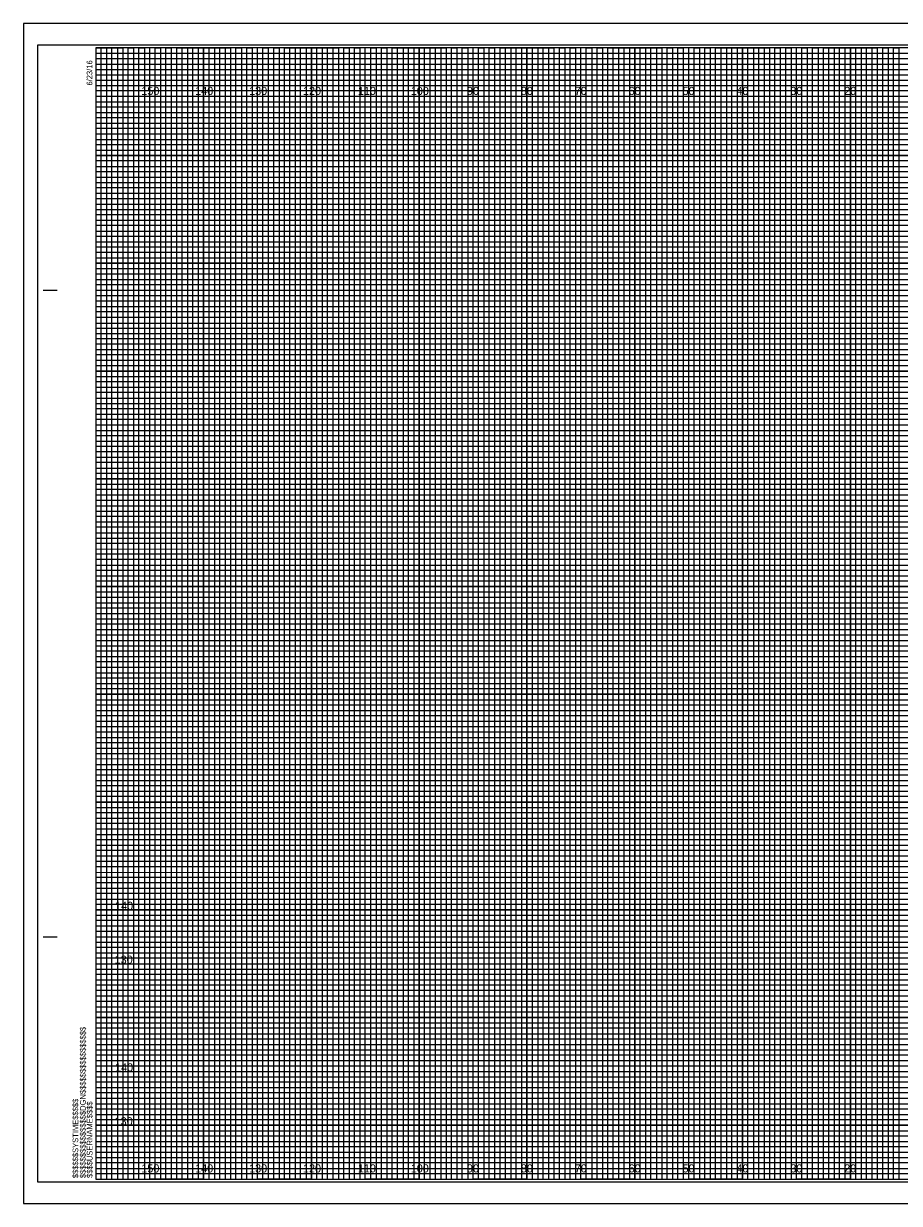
# Model space of a CAD drawing. Extents: x -13 to 323, y -5 to 2634.
# Drawn here: x -13.4 to 149.1, y 2415.5 to 2634.5 of the extents above; entities that cross this region are included whole.
import ezdxf

# ---------------------------------------------------------------- set-up
doc = ezdxf.new("R2010")
doc.units = 0
for name, color, linetype in [('Exist Cross Section Cell', 7, 'Continuous'), ('Exist XS Center Line Elevation Label', 7, 'Continuous'), ('Exist XS Ground Line', 7, 'Continuous'), ('Prop CMT Pvmt Surface Shoulder', 7, 'Continuous'), ('Prop CMT Pvmt Wedge Surface 3', 7, 'Continuous'), ('Prop CMT Shld Paved Course 1', 7, 'Continuous'), ('Prop CMT Shld Paved Course 2', 7, 'Continuous'), ('Prop CMT Shld Paved Course 3', 7, 'Continuous'), ('Prop CMT Slope Grass', 7, 'Continuous'), ('Prop CMT Subgrade Earthwork', 7, 'Continuous'), ('Scratch_Level_0', 7, 'Continuous')]:
    doc.layers.add(name, color=color, linetype=linetype)

msp = doc.modelspace()

# ---------------------------------------------------------------- linework, layer by layer
at = {"layer": 'Exist XS Center Line Elevation Label'}
for points in [[(0, 2630), (5, 2630), (5, 2420), (15, 2420), (15, 2630), (25, 2630), (25, 2420), (35, 2420), (35, 2630), (45, 2630), (45, 2420), (55, 2420), (55, 2630), (65, 2630), (65, 2420), (75, 2420), (75, 2630), (85, 2630), (85, 2420), (95, 2420), (95, 2630), (105, 2630), (105, 2420), (115, 2420), (115, 2630), (125, 2630), (125, 2420), (135, 2420), (135, 2630), (145, 2630), (145, 2420), (155, 2420)], [(0, 2625), (275, 2625)], [(0, 2605), (320, 2605), (320, 2615), (0, 2615)], [(0, 2585), (320, 2585), (320, 2595), (0, 2595)], [(0, 2565), (320, 2565), (320, 2575), (0, 2575)], [(0, 2545), (320, 2545), (320, 2555), (0, 2555)], [(0, 2525), (320, 2525), (320, 2535), (0, 2535)], [(0, 2505), (320, 2505), (320, 2515), (0, 2515)], [(0, 2485), (320, 2485), (320, 2495), (0, 2495)], [(0, 2465), (320, 2465), (320, 2475), (0, 2475)], [(0, 2445), (320, 2445), (320, 2455), (0, 2455)], [(0, 2425), (320, 2425), (320, 2435), (0, 2435)]]:
    msp.add_lwpolyline(points, dxfattribs=at)
at = {"layer": 'Exist XS Ground Line'}
for p, q in [((10, 2630), (0, 2630)), ((10, 2420), (10, 2630)), ((30, 2630), (20, 2630)), ((20, 2630), (20, 2420)), ((30, 2420), (30, 2630)), ((50, 2630), (40, 2630)), ((40, 2630), (40, 2420)), ((50, 2420), (50, 2630)), ((70, 2630), (60, 2630)), ((60, 2630), (60, 2420)), ((70, 2420), (70, 2630)), ((90, 2630), (80, 2630)), ((80, 2630), (80, 2420)), ((90, 2420), (90, 2630)), ((110, 2630), (100, 2630)), ((100, 2630), (100, 2420)), ((110, 2420), (110, 2630)), ((130, 2630), (120, 2630)), ((120, 2630), (120, 2420)), ((130, 2420), (130, 2630)), ((150, 2630), (140, 2630)), ((140, 2630), (140, 2420)), ((20, 2420), (10, 2420)), ((40, 2420), (30, 2420)), ((60, 2420), (50, 2420)), ((80, 2420), (70, 2420)), ((100, 2420), (90, 2420)), ((120, 2420), (110, 2420)), ((140, 2420), (130, 2420))]:
    msp.add_line(p, q, dxfattribs=at)
for points in [[(0, 2620), (320, 2620), (320, 2610), (0, 2610)], [(0, 2600), (320, 2600), (320, 2590), (0, 2590)], [(0, 2580), (320, 2580), (320, 2570), (0, 2570)], [(0, 2560), (320, 2560), (320, 2550), (0, 2550)], [(0, 2540), (320, 2540), (320, 2530), (0, 2530)], [(0, 2520), (320, 2520), (320, 2510), (0, 2510)], [(0, 2500), (320, 2500), (320, 2490), (0, 2490)], [(0, 2480), (320, 2480), (320, 2470), (0, 2470)], [(0, 2460), (320, 2460), (320, 2450), (0, 2450)], [(0, 2440), (320, 2440), (320, 2430), (0, 2430)]]:
    msp.add_lwpolyline(points, dxfattribs=at)
at = {"layer": 'Prop CMT Pvmt Surface Shoulder'}
for points in [[(0, 2420), (1, 2420), (1, 2630), (2, 2630), (2, 2420)], [(2, 2420), (3, 2420), (3, 2630), (4, 2630), (4, 2420)], [(5, 2420), (6, 2420), (6, 2630), (7, 2630), (7, 2420)], [(7, 2420), (8, 2420), (8, 2630), (9, 2630), (9, 2420)], [(10, 2420), (11, 2420), (11, 2630), (12, 2630), (12, 2420)], [(12, 2420), (13, 2420), (13, 2630), (14, 2630), (14, 2420)], [(15, 2420), (16, 2420), (16, 2630), (17, 2630), (17, 2420)], [(17, 2420), (18, 2420), (18, 2630), (19, 2630), (19, 2420)], [(20, 2420), (21, 2420), (21, 2630), (22, 2630), (22, 2420)], [(22, 2420), (23, 2420), (23, 2630), (24, 2630), (24, 2420)], [(25, 2420), (26, 2420), (26, 2630), (27, 2630), (27, 2420)], [(27, 2420), (28, 2420), (28, 2630), (29, 2630), (29, 2420)], [(30, 2420), (31, 2420), (31, 2630), (32, 2630), (32, 2420)], [(32, 2420), (33, 2420), (33, 2630), (34, 2630), (34, 2420)], [(35, 2420), (36, 2420), (36, 2630), (37, 2630), (37, 2420)], [(37, 2420), (38, 2420), (38, 2630), (39, 2630), (39, 2420)], [(40, 2420), (41, 2420), (41, 2630), (42, 2630), (42, 2420)], [(42, 2420), (43, 2420), (43, 2630), (44, 2630), (44, 2420)], [(45, 2420), (46, 2420), (46, 2630), (47, 2630), (47, 2420)], [(47, 2420), (48, 2420), (48, 2630), (49, 2630), (49, 2420)], [(50, 2420), (51, 2420), (51, 2630), (52, 2630), (52, 2420)], [(52, 2420), (53, 2420), (53, 2630), (54, 2630), (54, 2420)], [(55, 2420), (56, 2420), (56, 2630), (57, 2630), (57, 2420)], [(57, 2420), (58, 2420), (58, 2630), (59, 2630), (59, 2420)], [(60, 2420), (61, 2420), (61, 2630), (62, 2630), (62, 2420)], [(62, 2420), (63, 2420), (63, 2630), (64, 2630), (64, 2420)], [(65, 2420), (66, 2420), (66, 2630), (67, 2630), (67, 2420)], [(67, 2420), (68, 2420), (68, 2630), (69, 2630), (69, 2420)], [(70, 2420), (71, 2420), (71, 2630), (72, 2630), (72, 2420)], [(72, 2420), (73, 2420), (73, 2630), (74, 2630), (74, 2420)], [(75, 2420), (76, 2420), (76, 2630), (77, 2630), (77, 2420)], [(77, 2420), (78, 2420), (78, 2630), (79, 2630), (79, 2420)], [(80, 2420), (81, 2420), (81, 2630), (82, 2630), (82, 2420)], [(82, 2420), (83, 2420), (83, 2630), (84, 2630), (84, 2420)], [(85, 2420), (86, 2420), (86, 2630), (87, 2630), (87, 2420)], [(87, 2420), (88, 2420), (88, 2630), (89, 2630), (89, 2420)], [(90, 2420), (91, 2420), (91, 2630), (92, 2630), (92, 2420)], [(92, 2420), (93, 2420), (93, 2630), (94, 2630), (94, 2420)], [(95, 2420), (96, 2420), (96, 2630), (97, 2630), (97, 2420)], [(97, 2420), (98, 2420), (98, 2630), (99, 2630), (99, 2420)], [(100, 2420), (101, 2420), (101, 2630), (102, 2630), (102, 2420)], [(102, 2420), (103, 2420), (103, 2630), (104, 2630), (104, 2420)], [(105, 2420), (106, 2420), (106, 2630), (107, 2630), (107, 2420)], [(107, 2420), (108, 2420), (108, 2630), (109, 2630), (109, 2420)], [(110, 2420), (111, 2420), (111, 2630), (112, 2630), (112, 2420)], [(112, 2420), (113, 2420), (113, 2630), (114, 2630), (114, 2420)], [(115, 2420), (116, 2420), (116, 2630), (117, 2630), (117, 2420)], [(117, 2420), (118, 2420), (118, 2630), (119, 2630), (119, 2420)], [(120, 2420), (121, 2420), (121, 2630), (122, 2630), (122, 2420)], [(122, 2420), (123, 2420), (123, 2630), (124, 2630), (124, 2420)], [(125, 2420), (126, 2420), (126, 2630), (127, 2630), (127, 2420)], [(127, 2420), (128, 2420), (128, 2630), (129, 2630), (129, 2420)], [(130, 2420), (131, 2420), (131, 2630), (132, 2630), (132, 2420)], [(132, 2420), (133, 2420), (133, 2630), (134, 2630), (134, 2420)], [(135, 2420), (136, 2420), (136, 2630), (137, 2630), (137, 2420)], [(137, 2420), (138, 2420), (138, 2630), (139, 2630), (139, 2420)], [(140, 2420), (141, 2420), (141, 2630), (142, 2630), (142, 2420)], [(142, 2420), (143, 2420), (143, 2630), (144, 2630), (144, 2420)], [(145, 2420), (146, 2420), (146, 2630), (147, 2630), (147, 2420)], [(147, 2420), (148, 2420), (148, 2630), (149, 2630), (149, 2420)]]:
    msp.add_lwpolyline(points, dxfattribs=at)
at = {"layer": 'Prop CMT Pvmt Wedge Surface 3'}
for p, q in [((-9.8, 2585), (-7.3, 2585)), ((-9.7, 2585), (-7.2, 2585)), ((-9.8, 2465), (-7.3, 2465)), ((-9.7, 2465), (-7.2, 2465)), ((0, 2420), (0, 2420)), ((0, 2420), (0, 2420)), ((0, 2420), (0, 2420)), ((0, 2420), (0, 2420)), ((0, 2420), (0, 2420)), ((0, 2420), (0, 2420)), ((0, 2420), (0, 2420))]:
    msp.add_line(p, q, dxfattribs=at)
msp.add_lwpolyline([(320, 2630), (0, 2630), (0, 2420), (320, 2420)], close=True, dxfattribs=at)
at = {"layer": 'Prop CMT Shld Paved Course 1'}
for p, q in [((10, 2420), (10, 2630)), ((20, 2420), (20, 2630)), ((30, 2420), (30, 2630)), ((40, 2420), (40, 2630)), ((50, 2420), (50, 2630)), ((60, 2420), (60, 2630)), ((70, 2420), (70, 2630)), ((80, 2420), (80, 2630)), ((90, 2420), (90, 2630)), ((100, 2420), (100, 2630)), ((110, 2420), (110, 2630)), ((120, 2420), (120, 2630)), ((130, 2420), (130, 2630)), ((140, 2420), (140, 2630)), ((0, 2620), (320, 2620)), ((0, 2610), (320, 2610)), ((0, 2600), (320, 2600)), ((0, 2590), (320, 2590)), ((0, 2580), (320, 2580)), ((0, 2570), (320, 2570)), ((0, 2560), (320, 2560)), ((0, 2550), (320, 2550)), ((0, 2540), (320, 2540)), ((0, 2530), (320, 2530)), ((0, 2520), (320, 2520)), ((0, 2510), (320, 2510)), ((0, 2500), (320, 2500)), ((0, 2490), (320, 2490)), ((0, 2480), (320, 2480)), ((0, 2470), (320, 2470)), ((0, 2460), (320, 2460)), ((0, 2450), (320, 2450)), ((0, 2440), (320, 2440)), ((0, 2430), (320, 2430))]:
    msp.add_line(p, q, dxfattribs=at)
at = {"layer": 'Prop CMT Shld Paved Course 2'}
for p, q in [((323.3, 2634.5), (-13.4, 2634.5)), ((-13.4, 2634.5), (-13.4, 2415.5)), ((-13.4, 2415.5), (323.3, 2415.5))]:
    msp.add_line(p, q, dxfattribs=at)
at = {"layer": 'Prop CMT Slope Grass'}
msp.add_lwpolyline([(-10.8, 2419.5), (322.4, 2419.5), (322.4, 2630.5), (-10.8, 2630.5)], close=True, dxfattribs=at)
at = {"layer": 'Prop CMT Subgrade Earthwork'}
msp.add_lwpolyline([(-13.4, 2415.5), (323.3, 2415.5), (323.3, 2634.5), (-13.4, 2634.5)], close=True, dxfattribs=at)
at = {"layer": 'Scratch_Level_0'}
for p, q in [((0, 2629), (260, 2629)), ((260, 2627.98), (0, 2627.98)), ((0, 2627.98), (0, 2627)), ((0, 2627), (260, 2627)), ((260, 2625.89), (0, 2625.89)), ((0, 2625.89), (0, 2624)), ((0, 2624), (320, 2624))]:
    msp.add_line(p, q, dxfattribs=at)
for points in [[(0, 2623), (270, 2623), (320, 2623), (320, 2622), (0, 2622)], [(0, 2621), (320, 2621), (320, 2619), (0, 2619)], [(0, 2618), (320, 2618), (320, 2617), (0, 2616.98)], [(0, 2616), (320, 2616), (320, 2614), (0, 2614)], [(0, 2613), (320, 2613), (320, 2612), (0, 2612)], [(0, 2611), (320, 2611), (320, 2609), (0, 2609)], [(0, 2608), (320, 2608), (320, 2607), (0, 2607)], [(0, 2606), (320, 2606), (320, 2604), (0, 2604)], [(0, 2603), (320, 2603), (320, 2602), (0, 2602)], [(0, 2601), (320, 2601), (320, 2599), (0, 2599)], [(0, 2598), (320, 2598), (320, 2597), (0, 2597)], [(0, 2596), (320, 2596), (320, 2593.95), (320, 2593), (320, 2592), (0, 2592)], [(0, 2594), (320, 2594), (320, 2593), (0, 2593)], [(0, 2591), (320, 2591), (320, 2589), (0, 2589.03)], [(0, 2589.03), (320, 2589), (320, 2588), (0, 2588)], [(0, 2587), (320, 2587), (320, 2586), (0, 2586)], [(0, 2584), (320, 2584), (320, 2583), (0, 2583)], [(0, 2582), (320, 2582), (320, 2581), (0, 2581)], [(-0.07, 2578.89), (320, 2578.89), (320, 2577.88), (-0.07, 2577.88)], [(0, 2577), (320, 2577), (320, 2576), (0, 2576)], [(0, 2574), (320, 2574), (320, 2573), (0, 2573)], [(0, 2572), (320, 2572), (320, 2571), (0, 2571)], [(0, 2569), (320, 2569), (320, 2568), (0, 2568)], [(0, 2567), (320, 2567), (320, 2566), (0, 2566)], [(0, 2564), (320, 2564), (320, 2563), (0, 2563)], [(0, 2562), (320, 2562), (320, 2561), (0, 2561)], [(0, 2559), (320, 2559), (319.99, 2557.98), (0, 2558)], [(0, 2557), (320, 2557), (320, 2556), (0, 2556)], [(0, 2554), (320, 2554), (320, 2553), (0, 2553)], [(0, 2552), (320, 2552), (320, 2551), (0, 2551)], [(0, 2549), (320, 2549), (320, 2548), (0, 2548)], [(0, 2547), (320, 2547), (320, 2546), (0, 2546)], [(0, 2544), (320, 2544), (320, 2543), (0, 2543)], [(0, 2542), (320, 2542), (320, 2541), (0, 2541)], [(0, 2539), (320, 2539), (320, 2538), (0, 2538)], [(0, 2536.99), (320.07, 2536.91), (320, 2536), (0, 2536)], [(0, 2534), (320, 2534), (320, 2533), (0, 2533)], [(0, 2532), (320, 2532), (320, 2531), (0, 2531)], [(0, 2529), (320, 2529), (320, 2528), (0, 2528)], [(0, 2527), (320, 2527), (320, 2526), (0, 2526)], [(0, 2524), (320, 2524), (320, 2523), (0, 2523)], [(0, 2522), (320, 2522), (320, 2521), (0, 2521)], [(0, 2519), (320, 2519), (320, 2518), (0, 2518)], [(0, 2517), (320, 2517), (320, 2516), (0, 2516)], [(0, 2514), (320, 2514), (320, 2513), (0, 2513)], [(0, 2512), (320, 2512), (320, 2511), (0, 2511)], [(0, 2509), (320, 2509), (320, 2508), (0, 2508)], [(0, 2507), (320, 2507), (320, 2506), (0, 2506)], [(0, 2504), (320, 2504), (320, 2503), (0, 2503)], [(0, 2502), (320, 2502), (320, 2501), (0, 2501)], [(0, 2499), (320, 2499), (319.99, 2497.98), (0, 2498)], [(0, 2497), (320, 2497), (320, 2496), (0, 2496)], [(0, 2494), (320, 2494), (320, 2493), (0, 2493)], [(0, 2492), (320, 2492), (320, 2491), (0, 2491)], [(0, 2489), (320, 2489), (320, 2488), (0, 2488)], [(0, 2487), (320, 2487), (320, 2486), (0, 2486)], [(0, 2484), (320, 2484), (320, 2483), (0, 2483)], [(0, 2482), (320, 2482), (320, 2481), (0, 2481)], [(0, 2479), (320, 2479), (320, 2478), (0, 2478)], [(0, 2476.99), (320.07, 2476.91), (320, 2476), (0, 2476)], [(0, 2474), (320, 2474), (320, 2473), (0, 2473)], [(0, 2472), (320, 2472), (320, 2471), (0, 2471)], [(0, 2469), (320, 2469), (320, 2468), (0, 2468)], [(0, 2467), (320, 2467), (320, 2466), (0, 2466)], [(0, 2464), (320, 2464), (320, 2463), (0, 2463)], [(0, 2462), (320, 2462), (320, 2461), (0, 2461)], [(0, 2459), (320, 2459), (320, 2458), (0, 2458)], [(0, 2457), (320, 2457), (320, 2456), (0, 2456)], [(0, 2454), (320, 2454), (320, 2453), (0, 2453)], [(0, 2452), (320, 2452), (320, 2451), (0, 2451)], [(0, 2449), (320, 2449), (320, 2448), (0, 2448)], [(0, 2447), (320, 2447), (320, 2446), (0, 2446)], [(0, 2444), (320, 2444), (320, 2443), (0, 2443)], [(0, 2442), (320, 2442), (320, 2441), (0, 2441)], [(0, 2439), (320, 2439), (320, 2438), (0, 2438)], [(0, 2437), (320, 2437), (320, 2436), (0, 2436)], [(0, 2434), (320, 2434), (320, 2433), (0, 2433)], [(0, 2432), (320, 2432), (320, 2431), (0, 2431)], [(0, 2429), (320, 2429), (320, 2428), (0, 2428)], [(0, 2427), (320, 2427), (320, 2426), (0, 2426)], [(0, 2424), (320, 2424), (320, 2423), (0, 2423)], [(0, 2422), (320, 2422), (320, 2421), (0, 2421)]]:
    msp.add_lwpolyline(points, dxfattribs=at)

# ---------------------------------------------------------------- texts
at = {"layer": 'Exist Cross Section Cell'}
for s, p in [('150', (8.44, 2621.25)), ('140', (18.44, 2621.25)), ('130', (28.44, 2621.25)), ('120', (38.44, 2621.25)), ('110', (48.62, 2621.25)), ('100', (58.44, 2621.25)), ('90', (68.86, 2621.25)), ('80', (78.86, 2621.25)), ('70', (88.86, 2621.25)), ('60', (98.86, 2621.25)), ('50', (108.86, 2621.25)), ('40', (118.86, 2621.25)), ('30', (128.86, 2621.25)), ('20', (138.86, 2621.25)), ('150', (8.44, 2421.25)), ('140', (18.44, 2421.25)), ('130', (28.44, 2421.25)), ('120', (38.44, 2421.25)), ('110', (48.62, 2421.25)), ('100', (58.44, 2421.25)), ('90', (68.86, 2421.25)), ('80', (78.86, 2421.25)), ('70', (88.86, 2421.25)), ('60', (98.86, 2421.25)), ('50', (108.86, 2421.25)), ('40', (118.86, 2421.25)), ('30', (128.86, 2421.25)), ('20', (138.86, 2421.25))]:
    msp.add_text(s, height=1.5, dxfattribs=at).set_placement(p)
at = {"layer": 'Prop CMT Pvmt Wedge Surface 3'}
for s, p in [('6/23/16', (-0.65, 2623)), ('$$$$$$$$$$$$$$$$DGN$$$$$$$$$$$$$$$$', (-1.88, 2420.18)), ('$$$$$$SYSTIME$$$$$', (-3.26, 2420.18)), ('$$$$USERNAME$$$$', (-0.62, 2420.23))]:
    msp.add_text(s, height=1.05, rotation=90, dxfattribs=at).set_placement(p)
at = {"layer": 'Prop CMT Shld Paved Course 3'}
for s, p in [('140', (3.57, 2470)), ('130', (3.49, 2460)), ('140', (3.57, 2440)), ('130', (3.49, 2430))]:
    msp.add_text(s, height=1.5, dxfattribs=at).set_placement(p)

doc.saveas('drawing.dxf')
